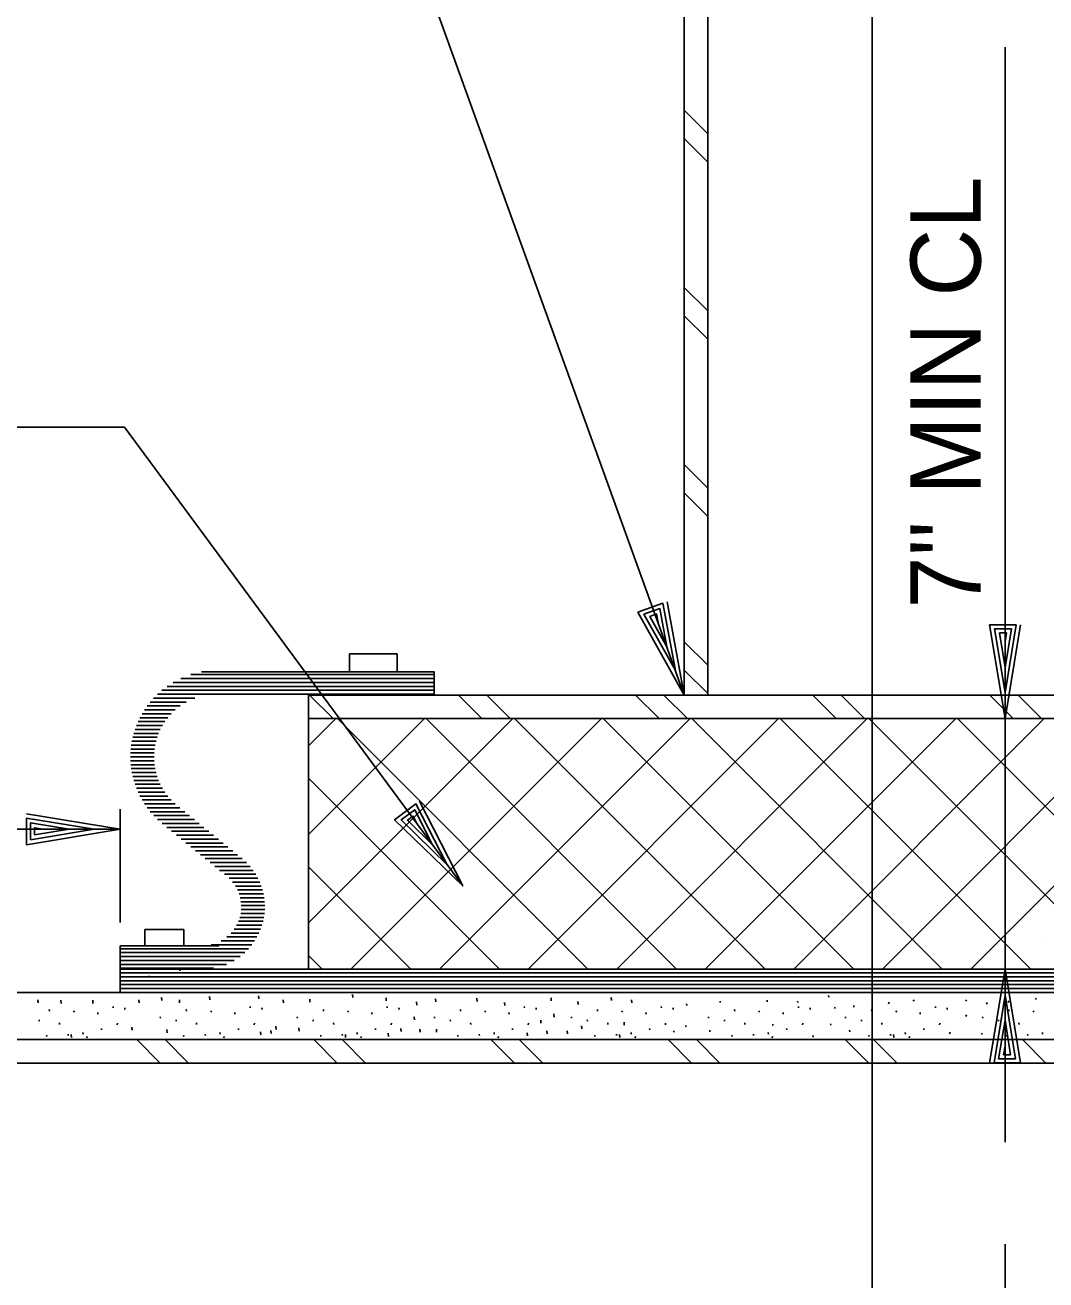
# Model space of a CAD drawing. Extents: x 22411.4 to 22495.4, y 22369.6 to 22415.
# Drawn here: x 22467.086 to 22469.803, y 22388.762 to 22392.101 of the extents above; entities that cross this region are included whole.
import ezdxf

# ---------------------------------------------------------------- set-up
doc = ezdxf.new("R2010")
doc.units = 0
for name, color, linetype in [('Level 1', 7, 'Continuous'), ('Level 2', 7, 'Continuous'), ('Level 4', 7, 'Continuous'), ('Level 8', 7, 'Continuous')]:
    doc.layers.add(name, color=color, linetype=linetype)

msp = doc.modelspace()

# ---------------------------------------------------------------- linework, layer by layer
at = {"layer": 'Level 1'}
for p, q in [((22469.3408, 22385.4019), (22469.3408, 22394.6266)), ((22469.6946, 22390.2559), (22469.6946, 22392.0425)), ((22467.9496, 22390.38), (22467.9496, 22390.4277)), ((22467.9496, 22390.4277), (22468.0771, 22390.4277)), ((22468.0771, 22390.38), (22468.0771, 22390.4277)), ((22468.8173, 22390.3836), (22468.8173, 22390.3836)), ((22468.8408, 22390.3184), (22468.8408, 22390.3184)), ((22469.6946, 22389.5892), (22469.6946, 22390.2559)), ((22467.3396, 22390.015), (22467.3396, 22389.7136)), ((22465.1325, 22389.9614), (22467.3396, 22389.9614)), ((22467.2702, 22389.9614), (22467.2702, 22389.9614)), ((22467.3396, 22389.9614), (22467.3396, 22389.9614)), ((22468.21, 22389.8665), (22468.21, 22389.8665)), ((22468.2512, 22389.8107), (22468.2512, 22389.8107)), ((22467.4056, 22389.6515), (22467.4056, 22389.6945)), ((22467.5093, 22389.6945), (22467.4056, 22389.6945)), ((22467.5093, 22389.6515), (22467.5093, 22389.6945)), ((22469.8025, 22389.6577), (22469.8025, 22389.6577)), ((22469.6946, 22389.129), (22469.6946, 22389.5892)), ((22469.792, 22389.5892), (22469.792, 22389.5892)), ((22469.6946, 22388.4225), (22469.6946, 22388.8574))]:
    msp.add_line(p, q, dxfattribs=at)
for points in [[(22469.7359, 22390.5052), (22469.6946, 22390.2559), (22469.6533, 22390.5052), (22469.7239, 22390.5052), (22469.6946, 22390.3252), (22469.6666, 22390.4945), (22469.7119, 22390.4945), (22469.6946, 22390.3919), (22469.6799, 22390.4839), (22469.6986, 22390.4839), (22469.6946, 22390.4612)], [(22467.0902, 22390.0027), (22467.3396, 22389.9614), (22467.0902, 22389.92), (22467.0902, 22389.9907), (22467.2702, 22389.9614), (22467.1009, 22389.9334), (22467.1009, 22389.9787), (22467.2036, 22389.9614), (22467.1116, 22389.9467), (22467.1116, 22389.9654), (22467.1342, 22389.9614)], [(22467.8774, 22389.5892), (22467.8409, 22389.6258)], [(22469.6533, 22389.3399), (22469.6946, 22389.5892), (22469.7359, 22389.3399), (22469.6653, 22389.3399), (22469.6946, 22389.5199), (22469.7226, 22389.3505), (22469.6773, 22389.3505), (22469.6946, 22389.4532), (22469.7093, 22389.3612), (22469.6906, 22389.3612), (22469.6946, 22389.3839)]]:
    msp.add_lwpolyline(points, dxfattribs=at)
at = {"layer": 'Level 2'}
for p, q in [((22468.8408, 22390.3184), (22468.8408, 22394.125)), ((22468.9033, 22390.3184), (22468.9033, 22394.125)), ((22468.8408, 22390.3184), (22467.9363, 22392.8208)), ((22465.4343, 22391.0309), (22467.3511, 22391.0309)), ((22467.3511, 22391.0309), (22468.2512, 22389.8107)), ((22468.1754, 22390.38), (22467.556, 22390.38)), ((22468.1754, 22390.3184), (22468.1754, 22390.38)), ((22469.3408, 22390.3184), (22467.8408, 22390.3184)), ((22467.8408, 22389.5892), (22467.8408, 22390.3184)), ((22469.3408, 22390.3184), (22470.8408, 22390.3184)), ((22469.3408, 22390.2559), (22467.8408, 22390.2559)), ((22469.3408, 22390.2559), (22470.8408, 22390.2559)), ((22467.6019, 22389.6515), (22467.3396, 22389.6515)), ((22467.3396, 22389.5267), (22467.3396, 22389.6515)), ((22471.3408, 22389.5892), (22467.3396, 22389.5892)), ((22467.4979, 22389.5848), (22467.4983, 22389.5889)), ((22467.4164, 22389.5672), (22467.4167, 22389.5712)), ((22472.4933, 22389.5267), (22466.1883, 22389.5267)), ((22469.3408, 22389.5267), (22466.295, 22389.5267)), ((22469.3408, 22389.4017), (22464.195, 22389.4017)), ((22469.3408, 22389.4017), (22474.4866, 22389.4017)), ((22469.3408, 22389.3392), (22464.2318, 22389.3392)), ((22469.3408, 22389.3392), (22474.4499, 22389.3392))]:
    msp.add_line(p, q, dxfattribs=at)
for points in [[(22468.795, 22390.5669), (22468.8408, 22390.3184), (22468.7172, 22390.5388), (22468.7837, 22390.5628), (22468.8173, 22390.3836), (22468.7334, 22390.5333), (22468.776, 22390.5487), (22468.7946, 22390.4463), (22468.7495, 22390.5278), (22468.7671, 22390.5342), (22468.771, 22390.5115)], [(22468.1742, 22390.3518), (22467.4806, 22390.3518)], [(22468.1742, 22390.3622), (22467.5006, 22390.3622)], [(22468.1742, 22390.3727), (22467.5277, 22390.3727)], [(22467.538, 22390.3102), (22467.4285, 22390.3102)], [(22468.1742, 22390.3206), (22467.4389, 22390.3206)], [(22468.1742, 22390.331), (22467.4507, 22390.331)], [(22468.1742, 22390.3414), (22467.4643, 22390.3414)], [(22467.4859, 22390.2789), (22467.4041, 22390.2789)], [(22467.499, 22390.2893), (22467.4113, 22390.2893)], [(22467.5154, 22390.2997), (22467.4194, 22390.2997)], [(22467.4584, 22390.2477), (22467.3871, 22390.2477)], [(22467.4661, 22390.2581), (22467.3921, 22390.2581)], [(22467.4751, 22390.2685), (22467.3977, 22390.2685)], [(22467.4417, 22390.2164), (22467.3758, 22390.2164)], [(22467.4463, 22390.2268), (22467.379, 22390.2268)], [(22467.4519, 22390.2372), (22467.3827, 22390.2372)], [(22467.4325, 22390.1852), (22467.3692, 22390.1852)], [(22467.4349, 22390.1956), (22467.3709, 22390.1956)], [(22467.4379, 22390.206), (22467.3731, 22390.206)], [(22467.4296, 22390.1539), (22467.3671, 22390.1539)], [(22467.4299, 22390.1643), (22467.3673, 22390.1643)], [(22467.4299, 22390.1435), (22467.3673, 22390.1435)], [(22467.4309, 22390.1747), (22467.368, 22390.1747)], [(22467.4309, 22390.1331), (22467.368, 22390.1331)], [(22467.4326, 22390.1227), (22467.3692, 22390.1227)], [(22467.4349, 22390.1122), (22467.3709, 22390.1122)], [(22467.438, 22390.1018), (22467.3731, 22390.1018)], [(22467.4418, 22390.0914), (22467.3758, 22390.0914)], [(22467.4464, 22390.081), (22467.379, 22390.081)], [(22467.452, 22390.0706), (22467.3828, 22390.0706)], [(22467.4585, 22390.0602), (22467.3872, 22390.0602)], [(22467.4662, 22390.0497), (22467.3922, 22390.0497)], [(22467.4753, 22390.0393), (22467.3978, 22390.0393)], [(22467.4861, 22390.0289), (22467.4042, 22390.0289)], [(22467.4987, 22390.0185), (22467.4114, 22390.0185)], [(22468.1364, 22390.0359), (22468.2512, 22389.8107), (22468.0699, 22389.9868), (22468.1268, 22390.0287), (22468.21, 22389.8665), (22468.087, 22389.9861), (22468.1235, 22390.013), (22468.1705, 22389.9201), (22468.104, 22389.9855), (22468.1191, 22389.9965), (22468.1293, 22389.9759)], [(22467.5114, 22390.0081), (22467.4196, 22390.0081)], [(22467.5242, 22389.9977), (22467.4287, 22389.9977)], [(22467.537, 22389.9872), (22467.4391, 22389.9872)], [(22467.5498, 22389.9768), (22467.4509, 22389.9768)], [(22467.5625, 22389.9664), (22467.4637, 22389.9664)], [(22467.5753, 22389.956), (22467.4764, 22389.956)], [(22467.5881, 22389.9456), (22467.4892, 22389.9456)], [(22467.6008, 22389.9352), (22467.502, 22389.9352)], [(22467.6136, 22389.9247), (22467.5147, 22389.9247)], [(22467.6264, 22389.9143), (22467.5275, 22389.9143)], [(22467.6391, 22389.9039), (22467.5403, 22389.9039)], [(22467.6519, 22389.8935), (22467.553, 22389.8935)], [(22467.6646, 22389.8831), (22467.5658, 22389.8831)], [(22467.676, 22389.8727), (22467.5786, 22389.8727)], [(22467.6854, 22389.8622), (22467.5913, 22389.8622)], [(22467.6935, 22389.8518), (22467.6041, 22389.8518)], [(22467.7003, 22389.8414), (22467.6168, 22389.8414)], [(22467.7061, 22389.831), (22467.6292, 22389.831)], [(22467.711, 22389.8206), (22467.6388, 22389.8206)], [(22467.715, 22389.8102), (22467.6462, 22389.8102)], [(22467.7183, 22389.7997), (22467.6519, 22389.7997)], [(22467.7208, 22389.7893), (22467.6561, 22389.7893)], [(22467.7226, 22389.7789), (22467.6591, 22389.7789)], [(22467.7238, 22389.7685), (22467.661, 22389.7685)], [(22467.7242, 22389.7477), (22467.6616, 22389.7477)], [(22467.7243, 22389.7581), (22467.6618, 22389.7581)], [(22467.7197, 22389.7164), (22467.6544, 22389.7164)], [(22467.7219, 22389.7268), (22467.6579, 22389.7268)], [(22467.7234, 22389.7372), (22467.6603, 22389.7372)], [(22467.7036, 22389.6747), (22467.6238, 22389.6747)], [(22467.7089, 22389.6852), (22467.6348, 22389.6852)], [(22467.7133, 22389.6956), (22467.6431, 22389.6956)], [(22467.7169, 22389.706), (22467.6495, 22389.706)], [(22467.6813, 22389.6435), (22467.3408, 22389.6435)], [(22467.69, 22389.6539), (22467.5818, 22389.6539)], [(22467.6974, 22389.6643), (22467.6085, 22389.6643)], [(22467.6711, 22389.6331), (22467.3408, 22389.6331)], [(22467.6587, 22389.6227), (22467.3408, 22389.6227)], [(22467.6433, 22389.6122), (22467.3408, 22389.6122)], [(22467.3396, 22389.5793), (22471.3408, 22389.5793)], [(22467.6228, 22389.6018), (22467.3408, 22389.6018)], [(22467.5882, 22389.5914), (22467.3408, 22389.5914)], [(22467.3396, 22389.5688), (22471.3408, 22389.5688)], [(22467.3396, 22389.5584), (22471.3408, 22389.5584)], [(22467.3396, 22389.548), (22471.3408, 22389.548)], [(22467.3396, 22389.5376), (22471.3408, 22389.5376)]]:
    msp.add_lwpolyline(points, dxfattribs=at)
at = {"layer": 'Level 8'}
for p, q in [((22467.4505, 22389.5056), (22467.4498, 22389.5138)), ((22467.5778, 22389.5078), (22467.5772, 22389.516)), ((22467.7085, 22389.51), (22467.7078, 22389.5182)), ((22467.8446, 22389.5012), (22467.8439, 22389.5094)), ((22467.9588, 22389.5133), (22467.9581, 22389.5215)), ((22468.0477, 22389.5045), (22468.0471, 22389.5127)), ((22468.1795, 22389.5023), (22468.1788, 22389.5105)), ((22468.2892, 22389.5034), (22468.2886, 22389.5116)), ((22468.4869, 22389.5045), (22468.4862, 22389.5127)), ((22468.6471, 22389.5056), (22468.6465, 22389.5138)), ((22469.2251, 22389.5145), (22469.2248, 22389.5186)), ((22469.4503, 22389.5038), (22469.4522, 22389.5077)), ((22469.5898, 22389.5038), (22469.5916, 22389.5077)), ((22469.7753, 22389.5082), (22469.7771, 22389.5121)), ((22467.1211, 22389.499), (22467.1205, 22389.5072)), ((22467.1512, 22389.4775), (22467.1508, 22389.4816)), ((22467.1826, 22389.4979), (22467.1819, 22389.5061)), ((22467.2157, 22389.4742), (22467.2176, 22389.4781)), ((22467.2671, 22389.4979), (22467.2665, 22389.5061)), ((22467.321, 22389.4857), (22467.3207, 22389.4897)), ((22467.3522, 22389.4816), (22467.3519, 22389.4857)), ((22467.3901, 22389.499), (22467.3894, 22389.5072)), ((22467.4977, 22389.499), (22467.497, 22389.5072)), ((22467.5159, 22389.4775), (22467.5156, 22389.4816)), ((22467.5805, 22389.4742), (22467.5823, 22389.4781)), ((22467.6857, 22389.4857), (22467.6854, 22389.4897)), ((22467.717, 22389.4816), (22467.7167, 22389.4857)), ((22467.7744, 22389.499), (22467.7737, 22389.5072)), ((22467.8807, 22389.4775), (22467.8803, 22389.4816)), ((22467.9452, 22389.4742), (22467.9471, 22389.4781)), ((22468.0505, 22389.4857), (22468.0502, 22389.4897)), ((22468.0817, 22389.4816), (22468.0814, 22389.4857)), ((22468.129, 22389.4935), (22468.1283, 22389.5017)), ((22468.2454, 22389.4775), (22468.2451, 22389.4816)), ((22468.31, 22389.4742), (22468.3118, 22389.4781)), ((22468.3628, 22389.4924), (22468.3621, 22389.5006)), ((22468.4152, 22389.4857), (22468.4149, 22389.4897)), ((22468.4465, 22389.4816), (22468.4462, 22389.4857)), ((22468.5582, 22389.4946), (22468.5576, 22389.5028)), ((22468.6102, 22389.4775), (22468.6098, 22389.4816)), ((22468.6747, 22389.4742), (22468.6766, 22389.4781)), ((22468.7009, 22389.499), (22468.7003, 22389.5072)), ((22468.78, 22389.4857), (22468.7797, 22389.4897)), ((22468.8112, 22389.4816), (22468.8109, 22389.4857)), ((22468.8475, 22389.4926), (22468.8471, 22389.4966)), ((22468.9364, 22389.5002), (22468.9361, 22389.5043)), ((22468.9749, 22389.4775), (22468.9746, 22389.4816)), ((22469.0395, 22389.4742), (22469.0413, 22389.4781)), ((22469.0616, 22389.5024), (22469.0612, 22389.5065)), ((22469.1428, 22389.5002), (22469.1425, 22389.5043)), ((22469.1447, 22389.4857), (22469.1444, 22389.4897)), ((22469.176, 22389.4816), (22469.1757, 22389.4857)), ((22469.2407, 22389.484), (22469.2425, 22389.488)), ((22469.2921, 22389.4882), (22469.2918, 22389.4922)), ((22469.3397, 22389.4775), (22469.3393, 22389.4816)), ((22469.3845, 22389.4972), (22469.3863, 22389.5011)), ((22469.4042, 22389.4742), (22469.4061, 22389.4781)), ((22469.5095, 22389.4857), (22469.5092, 22389.4897)), ((22469.5407, 22389.4816), (22469.5404, 22389.4857)), ((22469.6447, 22389.4961), (22469.6465, 22389.5)), ((22469.7029, 22389.5005), (22469.7047, 22389.5044)), ((22469.7044, 22389.4775), (22469.7041, 22389.4816)), ((22469.769, 22389.4742), (22469.7708, 22389.4781)), ((22467.124, 22389.4503), (22467.1237, 22389.4544)), ((22467.1783, 22389.4422), (22467.178, 22389.4462)), ((22467.2802, 22389.4693), (22467.2799, 22389.4734)), ((22467.3314, 22389.4406), (22467.3322, 22389.4454)), ((22467.4466, 22389.4585), (22467.4462, 22389.4626)), ((22467.4887, 22389.4503), (22467.4884, 22389.4544)), ((22467.5431, 22389.4422), (22467.5427, 22389.4462)), ((22467.645, 22389.4693), (22467.6447, 22389.4734)), ((22467.6962, 22389.4406), (22467.6969, 22389.4454)), ((22467.8113, 22389.4585), (22467.811, 22389.4626)), ((22467.8535, 22389.4503), (22467.8532, 22389.4544)), ((22467.9078, 22389.4422), (22467.9075, 22389.4462)), ((22468.0097, 22389.4693), (22468.0094, 22389.4734)), ((22468.0609, 22389.4406), (22468.0617, 22389.4454)), ((22468.1224, 22389.454), (22468.1217, 22389.4622)), ((22468.1761, 22389.4585), (22468.1757, 22389.4626)), ((22468.2182, 22389.4503), (22468.2179, 22389.4544)), ((22468.2726, 22389.4422), (22468.2722, 22389.4462)), ((22468.3745, 22389.4693), (22468.3742, 22389.4734)), ((22468.4257, 22389.4406), (22468.4264, 22389.4454)), ((22468.4594, 22389.4452), (22468.4587, 22389.4534)), ((22468.4945, 22389.4617), (22468.4939, 22389.4698)), ((22468.5408, 22389.4585), (22468.5405, 22389.4626)), ((22468.583, 22389.4503), (22468.5827, 22389.4544)), ((22468.6373, 22389.4422), (22468.637, 22389.4462)), ((22468.6812, 22389.4397), (22468.6805, 22389.4479)), ((22468.7392, 22389.4693), (22468.7389, 22389.4734)), ((22468.7904, 22389.4406), (22468.7912, 22389.4454)), ((22468.9056, 22389.4585), (22468.9052, 22389.4626)), ((22468.9477, 22389.4503), (22468.9474, 22389.4544)), ((22469.0021, 22389.4422), (22469.0017, 22389.4462)), ((22469.0769, 22389.4388), (22469.0766, 22389.4428)), ((22469.104, 22389.4693), (22469.1037, 22389.4734)), ((22469.1552, 22389.4406), (22469.1559, 22389.4454)), ((22469.2306, 22389.4399), (22469.2303, 22389.4439)), ((22469.2703, 22389.4585), (22469.27, 22389.4626)), ((22469.3125, 22389.4503), (22469.3122, 22389.4544)), ((22469.3668, 22389.4422), (22469.3665, 22389.4462)), ((22469.4687, 22389.4693), (22469.4684, 22389.4734)), ((22469.5199, 22389.4406), (22469.5207, 22389.4454)), ((22469.5898, 22389.4632), (22469.5916, 22389.4671)), ((22469.6351, 22389.4585), (22469.6347, 22389.4626)), ((22469.6772, 22389.4503), (22469.6769, 22389.4544)), ((22469.7316, 22389.4422), (22469.7312, 22389.4462)), ((22467.1437, 22389.4102), (22467.1441, 22389.4138)), ((22467.2014, 22389.4122), (22467.2011, 22389.4163)), ((22467.2101, 22389.4068), (22467.2094, 22389.415)), ((22467.2408, 22389.4163), (22467.2405, 22389.4204)), ((22467.2502, 22389.406), (22467.2527, 22389.4102)), ((22467.2897, 22389.4272), (22467.2894, 22389.4313)), ((22467.3714, 22389.4266), (22467.3708, 22389.4347)), ((22467.4648, 22389.42), (22467.4641, 22389.4281)), ((22467.5085, 22389.4102), (22467.5088, 22389.4138)), ((22467.5662, 22389.4122), (22467.5658, 22389.4163)), ((22467.6056, 22389.4163), (22467.6052, 22389.4204)), ((22467.6149, 22389.406), (22467.6174, 22389.4102)), ((22467.6545, 22389.4272), (22467.6542, 22389.4313)), ((22467.714, 22389.4145), (22467.7133, 22389.4226)), ((22467.7414, 22389.4178), (22467.7408, 22389.4259)), ((22467.7546, 22389.4288), (22467.7539, 22389.4369)), ((22467.8161, 22389.4244), (22467.8154, 22389.4325)), ((22467.8732, 22389.4102), (22467.8736, 22389.4138)), ((22467.9309, 22389.4122), (22467.9306, 22389.4163)), ((22467.9396, 22389.4068), (22467.9389, 22389.415)), ((22467.9703, 22389.4163), (22467.97, 22389.4204)), ((22467.9797, 22389.406), (22467.9822, 22389.4102)), ((22468.0192, 22389.4272), (22468.0189, 22389.4313)), ((22468.0532, 22389.4101), (22468.0525, 22389.4183)), ((22468.0872, 22389.4233), (22468.0866, 22389.4314)), ((22468.1377, 22389.4211), (22468.1371, 22389.4292)), ((22468.1817, 22389.4211), (22468.181, 22389.4292)), ((22468.238, 22389.4102), (22468.2383, 22389.4138)), ((22468.2957, 22389.4122), (22468.2953, 22389.4163)), ((22468.3351, 22389.4163), (22468.3347, 22389.4204)), ((22468.3444, 22389.406), (22468.3469, 22389.4102)), ((22468.384, 22389.4272), (22468.3837, 22389.4313)), ((22468.4232, 22389.4112), (22468.4225, 22389.4193)), ((22468.4759, 22389.4167), (22468.4752, 22389.4248)), ((22468.5297, 22389.4167), (22468.529, 22389.4248)), ((22468.5681, 22389.4298), (22468.5674, 22389.438)), ((22468.6027, 22389.4102), (22468.6031, 22389.4138)), ((22468.6604, 22389.4122), (22468.6601, 22389.4163)), ((22468.6691, 22389.4068), (22468.6684, 22389.415)), ((22468.6998, 22389.4163), (22468.6995, 22389.4204)), ((22468.7092, 22389.406), (22468.7117, 22389.4102)), ((22468.7487, 22389.4272), (22468.7484, 22389.4313)), ((22468.8134, 22389.4212), (22468.8131, 22389.4253)), ((22468.8453, 22389.4355), (22468.8449, 22389.4395)), ((22468.9089, 22389.4223), (22468.9086, 22389.4264)), ((22468.9675, 22389.4102), (22468.9678, 22389.4138)), ((22469.0252, 22389.4122), (22469.0248, 22389.4163)), ((22469.0646, 22389.4163), (22469.0642, 22389.4204)), ((22469.0739, 22389.406), (22469.0764, 22389.4102)), ((22469.1135, 22389.4272), (22469.1132, 22389.4313)), ((22469.1834, 22389.408), (22469.1831, 22389.4121)), ((22469.2811, 22389.4223), (22469.2808, 22389.4264)), ((22469.3322, 22389.4102), (22469.3326, 22389.4138)), ((22469.3899, 22389.4122), (22469.3896, 22389.4163)), ((22469.3986, 22389.4068), (22469.3979, 22389.415)), ((22469.4293, 22389.4163), (22469.429, 22389.4204)), ((22469.4387, 22389.406), (22469.4412, 22389.4102)), ((22469.4782, 22389.4272), (22469.4779, 22389.4313)), ((22469.547, 22389.4171), (22469.5488, 22389.421)), ((22469.6315, 22389.4149), (22469.6333, 22389.4188)), ((22469.697, 22389.4102), (22469.6973, 22389.4138)), ((22469.7547, 22389.4122), (22469.7543, 22389.4163)), ((22469.7941, 22389.4163), (22469.7937, 22389.4204))]:
    msp.add_line(p, q, dxfattribs=at)
for points in [[(22468.9033, 22391.812), (22468.8408, 22391.8745)], [(22468.9033, 22391.7366), (22468.8408, 22391.7991)], [(22468.9033, 22391.3406), (22468.8408, 22391.4031)], [(22468.9033, 22391.2652), (22468.8408, 22391.3277)], [(22468.9033, 22390.8692), (22468.8408, 22390.9317)], [(22468.9033, 22390.7938), (22468.8408, 22390.8563)], [(22468.9033, 22390.3978), (22468.8408, 22390.4603)], [(22468.9033, 22390.3224), (22468.8408, 22390.3849)], [(22467.9062, 22390.2559), (22467.8437, 22390.3184)], [(22468.3022, 22390.2559), (22468.2397, 22390.3184)], [(22468.3776, 22390.2559), (22468.3151, 22390.3184)], [(22468.7736, 22390.2559), (22468.7111, 22390.3184)], [(22468.849, 22390.2559), (22468.7865, 22390.3184)], [(22469.245, 22390.2559), (22469.1825, 22390.3184)], [(22469.3204, 22390.2559), (22469.2579, 22390.3184)], [(22469.7164, 22390.2559), (22469.6539, 22390.3184)], [(22469.7918, 22390.2559), (22469.7293, 22390.3184)], [(22467.8408, 22389.712), (22468.3848, 22390.2559)], [(22467.8408, 22389.9477), (22468.1491, 22390.2559)], [(22467.8408, 22390.1834), (22467.9134, 22390.2559)], [(22468.5845, 22389.5892), (22467.9179, 22390.2559)], [(22467.9538, 22389.5892), (22468.6205, 22390.2559)], [(22468.8202, 22389.5892), (22468.1536, 22390.2559)], [(22468.1895, 22389.5892), (22468.8562, 22390.2559)], [(22469.0559, 22389.5892), (22468.3893, 22390.2559)], [(22468.4252, 22389.5892), (22469.0919, 22390.2559)], [(22469.2916, 22389.5892), (22468.625, 22390.2559)], [(22468.6609, 22389.5892), (22469.3276, 22390.2559)], [(22469.5273, 22389.5892), (22468.8607, 22390.2559)], [(22468.8966, 22389.5892), (22469.5633, 22390.2559)], [(22469.763, 22389.5892), (22469.0964, 22390.2559)], [(22469.1323, 22389.5892), (22469.799, 22390.2559)], [(22469.9988, 22389.5892), (22469.3321, 22390.2559)], [(22469.368, 22389.5892), (22470.0347, 22390.2559)], [(22470.2344, 22389.5892), (22469.5678, 22390.2559)], [(22469.6037, 22389.5892), (22470.2704, 22390.2559)], [(22468.3488, 22389.5892), (22467.8409, 22390.0972)], [(22468.1131, 22389.5892), (22467.8409, 22389.8615)], [(22467.446, 22389.3392), (22467.3835, 22389.4017)], [(22467.5214, 22389.3392), (22467.4589, 22389.4017)], [(22467.9174, 22389.3392), (22467.8549, 22389.4017)], [(22467.9928, 22389.3392), (22467.9303, 22389.4017)], [(22468.3888, 22389.3392), (22468.3263, 22389.4017)], [(22468.4642, 22389.3392), (22468.4017, 22389.4017)], [(22468.8602, 22389.3392), (22468.7977, 22389.4017)], [(22468.9356, 22389.3392), (22468.8731, 22389.4017)], [(22469.3316, 22389.3392), (22469.2691, 22389.4017)], [(22469.407, 22389.3392), (22469.3445, 22389.4017)], [(22469.803, 22389.3392), (22469.7405, 22389.4017)]]:
    msp.add_lwpolyline(points, dxfattribs=at)

# ---------------------------------------------------------------- texts
at = {"layer": 'Level 4'}
msp.add_text("7'' MIN CL", height=0.18667, rotation=90, dxfattribs=at).set_placement((22469.6295, 22390.5484))

doc.saveas('drawing.dxf')
